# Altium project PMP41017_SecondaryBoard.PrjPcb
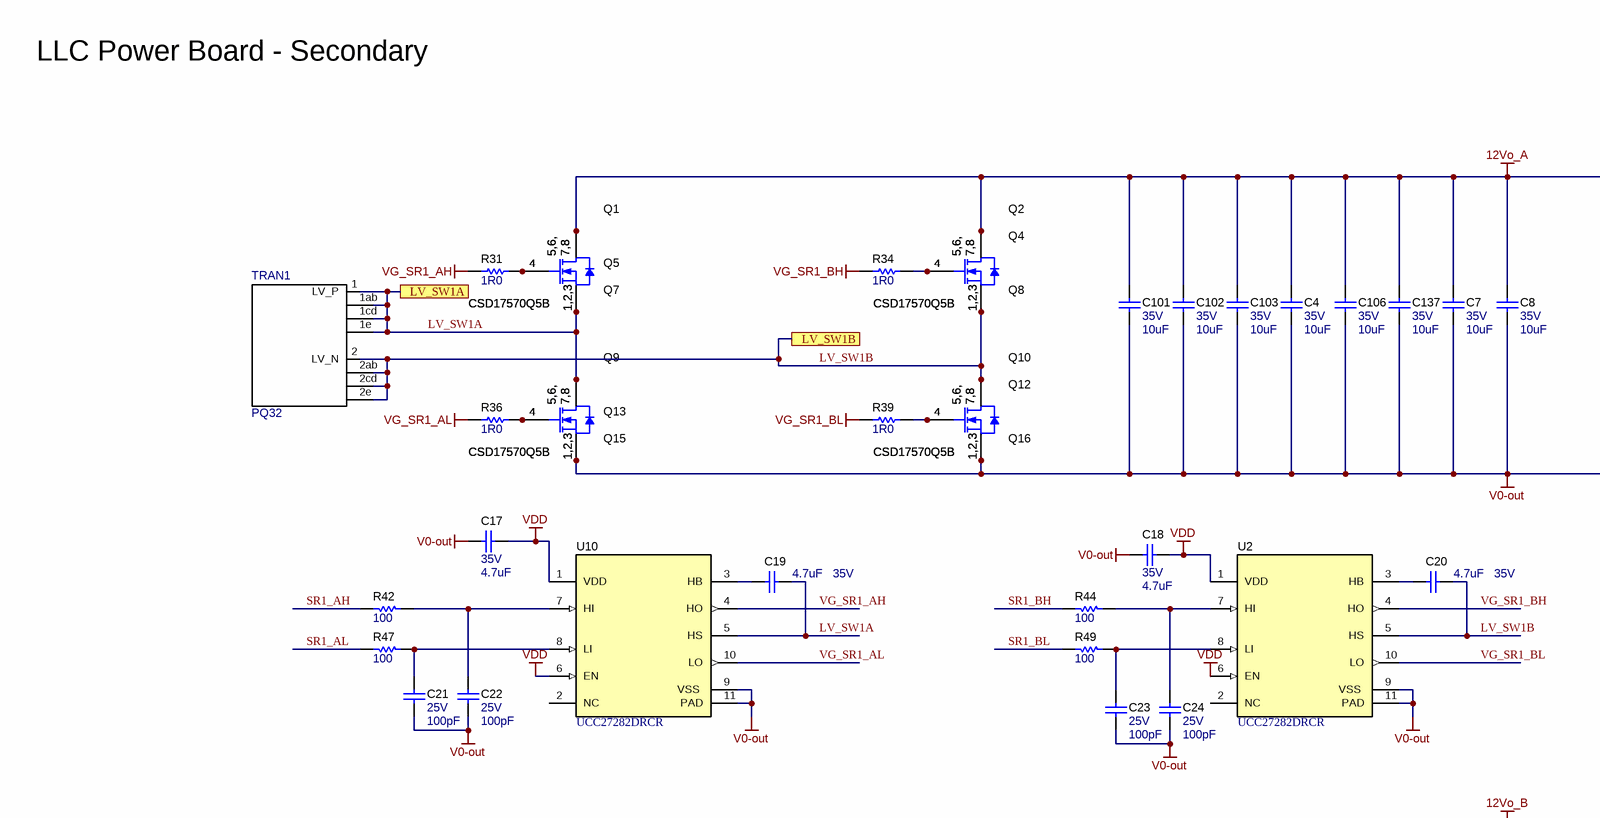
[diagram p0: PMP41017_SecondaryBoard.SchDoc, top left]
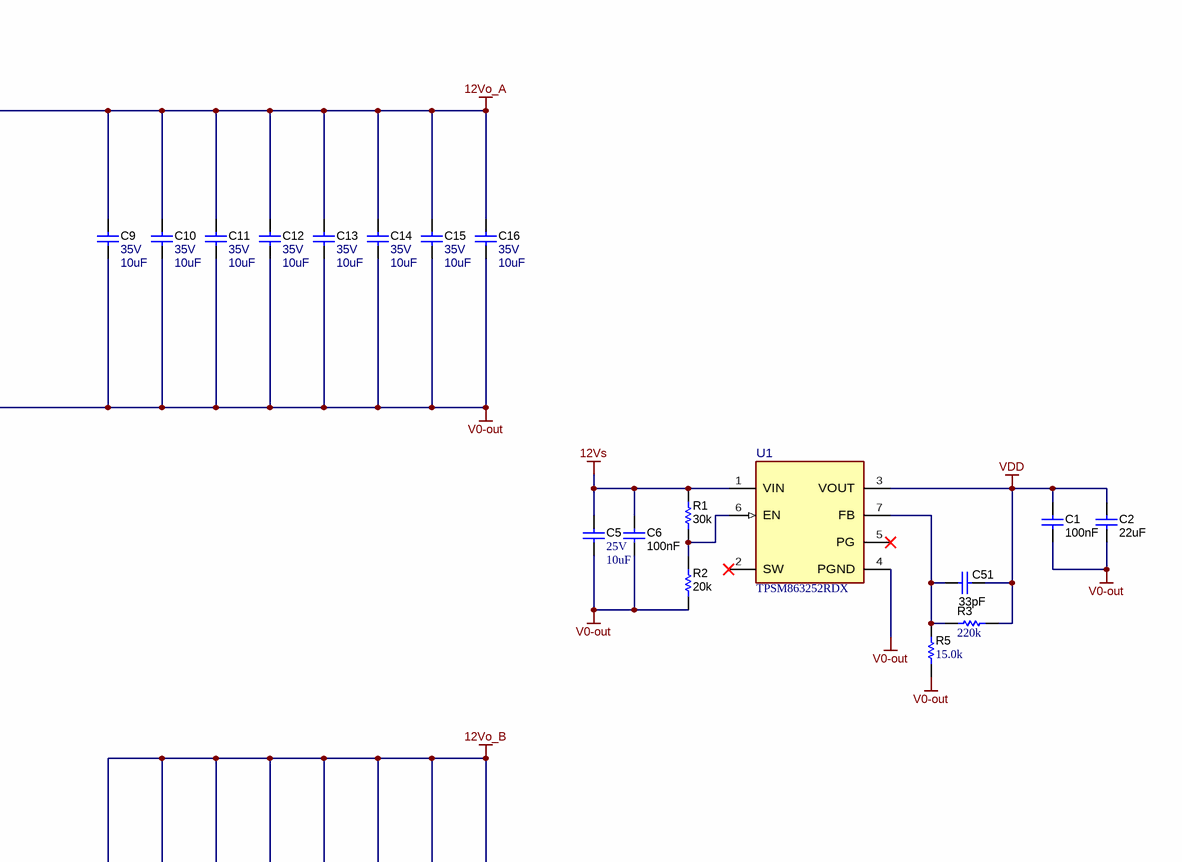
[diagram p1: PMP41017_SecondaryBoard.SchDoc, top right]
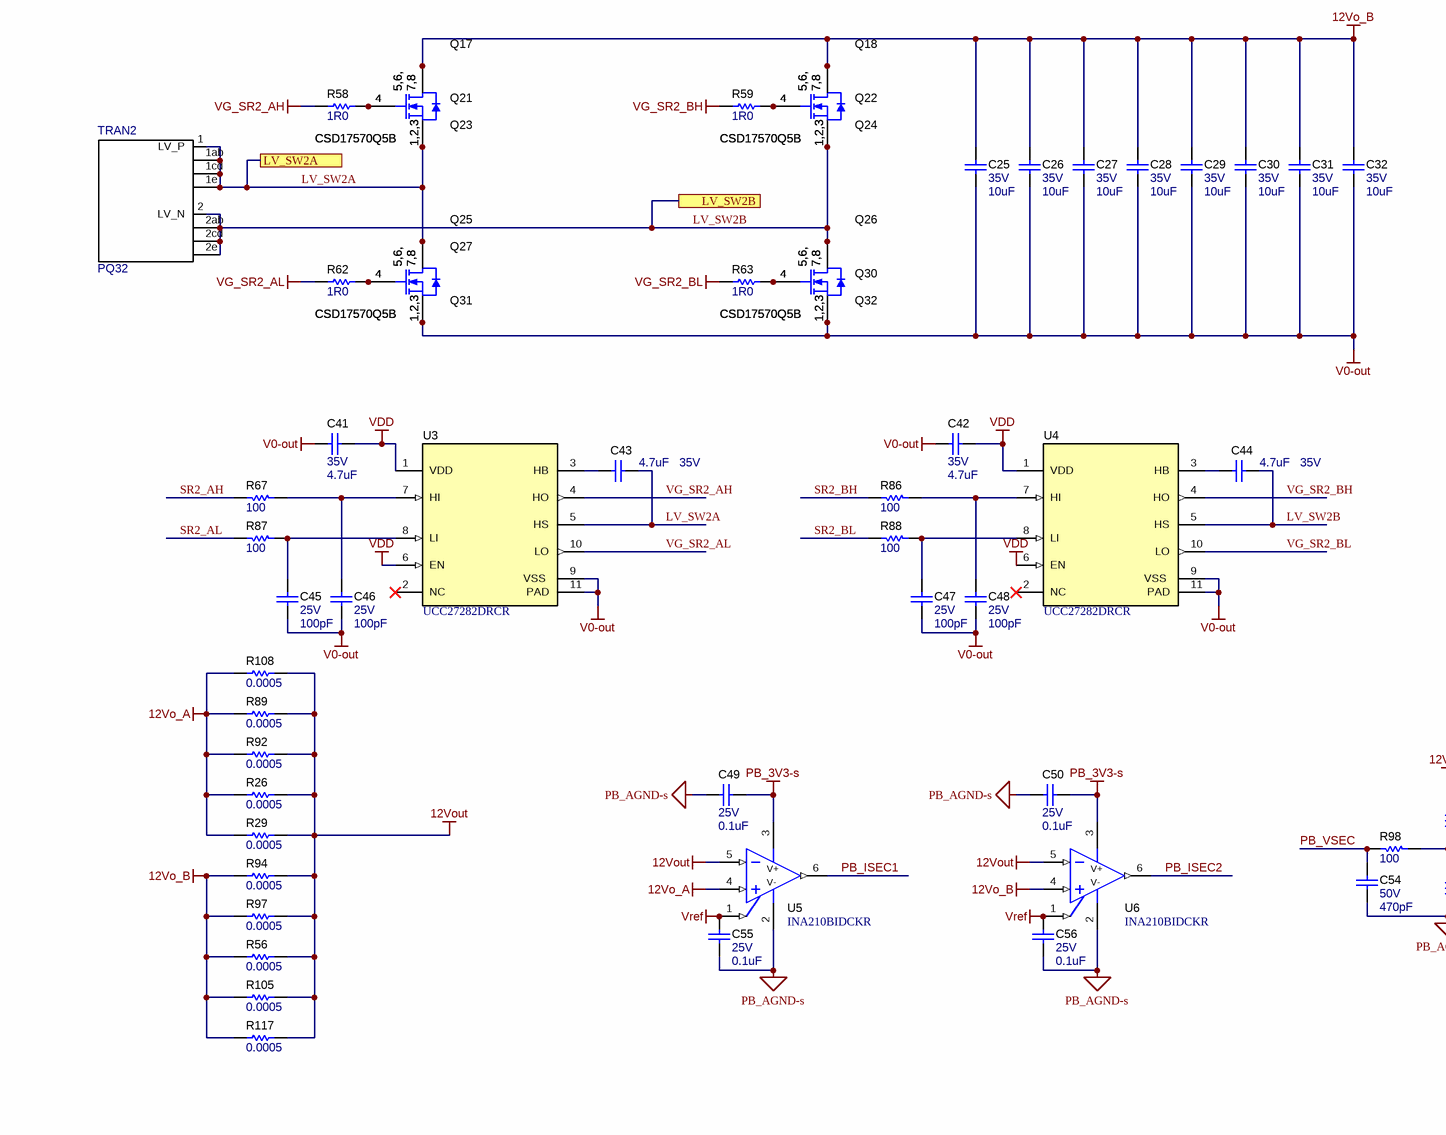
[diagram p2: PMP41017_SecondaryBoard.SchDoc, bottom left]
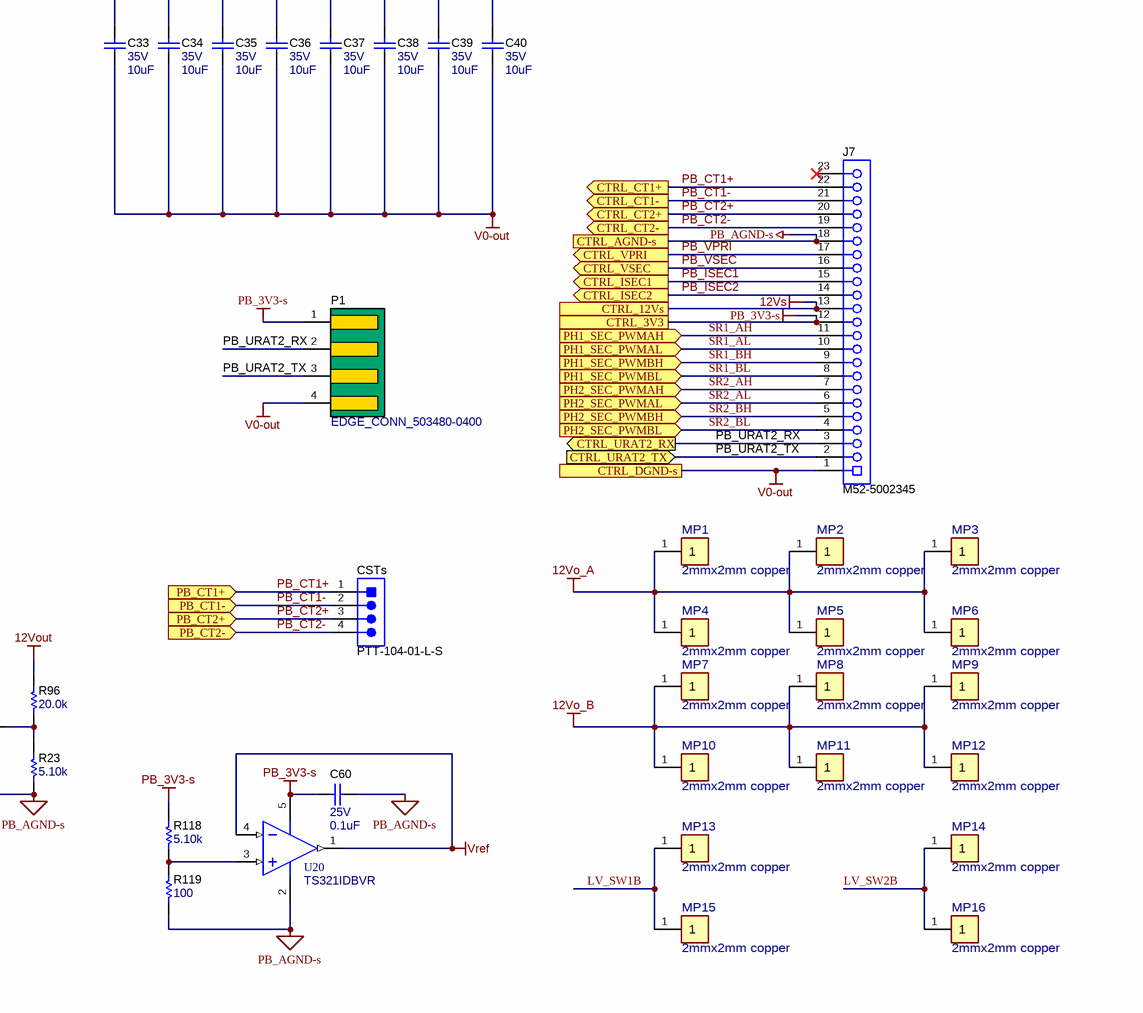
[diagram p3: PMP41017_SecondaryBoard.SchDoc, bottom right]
CopyrightYear: 2022; PCB_Layout: Desheng Guo; PCB_Rev: E1; PRJ_Customer: Public Release; PRJ_Engineer: Desheng Guo; PRJ_Number: PMP41017; PRJ_Title: CRPS 12V 3000W LLC; SCH_Rev: E1; TechSupport: http://www.ti.com/support; TID: N/A
1 sheet, 147 parts. Net scope: flat (ports and power ports of the same name join across sheets).
Board files: PMP41017_SecondaryBoard_Cyntec20230129.PcbDoc, PMP41017_SecondaryBoard.PcbDoc

## Sheet PMP41017_SecondaryBoard.SchDoc
size A2; Date: Not shown in title block; ApprovedBy: Not shown in title block; CheckedBy: Not shown in title block; Author: Not shown in title block; CompanyName: Not shown in title block; Engineer: Not shown in title block; Organization: Not shown in title block; Address1: Not shown in title block; Address2: Not shown in title block; Address3: Not shown in title block; Address4: Not shown in title block; DocumentNumber: 1; Revision: Use project parameter SCH_Rev; SheetNumber: 1; SheetTotal: 1; PageSetup: Record=PageOptions¦CenterHorizontal=True¦CenterVertical=True¦PrintScale=0.69¦XCorrection=1.00¦YCorrection=1.00¦PrintKind=0¦BorderSize=5000000¦LeftOffset=0¦BottomOffset=0¦Orientation=2¦PaperLength=1000¦PaperWidth=1000¦Scale=100¦PaperSource=15¦PrintQuality=600¦MediaType=1¦DitherType=10¦PaperKind=Letter¦PrintScaleMode=1

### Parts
C1  Cap_F: 100nF  [0603]  (hidden comment: C0603C104K5RACTU)
C2  ValueDisplayed: 22uF  [0805_HV]  (hidden comment: GRM21BC81C226ME44L)
C4  VDC_V: 35V  ValueDisplayed: 10uF  [1206_190]  (hidden comment: GMK316AB7106KL-TR)
C5  VDC_V: 25V  ValueDisplayed: 10uF  [0603]  (hidden comment: C1608X5R1E106M080AC)
C6  Cap_F: 100nF  [0603]  (hidden comment: C0603C104K5RACTU)
C7  VDC_V: 35V  ValueDisplayed: 10uF  [1206_190]  (hidden comment: GMK316AB7106KL-TR)
C8  VDC_V: 35V  ValueDisplayed: 10uF  [1206_190]  (hidden comment: GMK316AB7106KL-TR)
C9  VDC_V: 35V  ValueDisplayed: 10uF  [1206_190]  (hidden comment: GMK316AB7106KL-TR)
C10  VDC_V: 35V  ValueDisplayed: 10uF  [1206_190]  (hidden comment: GMK316AB7106KL-TR)
C11  VDC_V: 35V  ValueDisplayed: 10uF  [1206_190]  (hidden comment: GMK316AB7106KL-TR)
C12  VDC_V: 35V  ValueDisplayed: 10uF  [1206_190]  (hidden comment: GMK316AB7106KL-TR)
C13  VDC_V: 35V  ValueDisplayed: 10uF  [1206_190]  (hidden comment: GMK316AB7106KL-TR)
C14  VDC_V: 35V  ValueDisplayed: 10uF  [1206_190]  (hidden comment: GMK316AB7106KL-TR)
C15  VDC_V: 35V  ValueDisplayed: 10uF  [1206_190]  (hidden comment: GMK316AB7106KL-TR)
C16  VDC_V: 35V  ValueDisplayed: 10uF  [1206_190]  (hidden comment: GMK316AB7106KL-TR)
C17  VDC_V: 35V  ValueDisplayed: 4.7uF  [0805_HV]  (hidden comment: C2012X7R1V475K125AC)
C18  VDC_V: 35V  ValueDisplayed: 4.7uF  [0805_HV]  (hidden comment: C2012X7R1V475K125AC)
C19  VDC_V: 35V  ValueDisplayed: 4.7uF  [0805_HV]  (hidden comment: C2012X7R1V475K125AC)
C20  VDC_V: 35V  ValueDisplayed: 4.7uF  [0805_HV]  (hidden comment: C2012X7R1V475K125AC)
C21  VDC_V: 25V  ValueDisplayed: 100pF  [0603]  (hidden comment: CGA3E2C0G1H101J080AA)
C22  VDC_V: 25V  ValueDisplayed: 100pF  [0603]  (hidden comment: CGA3E2C0G1H101J080AA)
C23  VDC_V: 25V  ValueDisplayed: 100pF  [0603]  (hidden comment: CGA3E2C0G1H101J080AA)
C24  VDC_V: 25V  ValueDisplayed: 100pF  [0603]  (hidden comment: CGA3E2C0G1H101J080AA)
C25  VDC_V: 35V  ValueDisplayed: 10uF  [1206_190]  (hidden comment: GMK316AB7106KL-TR)
C26  VDC_V: 35V  ValueDisplayed: 10uF  [1206_190]  (hidden comment: GMK316AB7106KL-TR)
C27  VDC_V: 35V  ValueDisplayed: 10uF  [1206_190]  (hidden comment: GMK316AB7106KL-TR)
C28  VDC_V: 35V  ValueDisplayed: 10uF  [1206_190]  (hidden comment: GMK316AB7106KL-TR)
C29  VDC_V: 35V  ValueDisplayed: 10uF  [1206_190]  (hidden comment: GMK316AB7106KL-TR)
C30  VDC_V: 35V  ValueDisplayed: 10uF  [1206_190]  (hidden comment: GMK316AB7106KL-TR)
C31  VDC_V: 35V  ValueDisplayed: 10uF  [1206_190]  (hidden comment: GMK316AB7106KL-TR)
C32  VDC_V: 35V  ValueDisplayed: 10uF  [1206_190]  (hidden comment: GMK316AB7106KL-TR)
C33  VDC_V: 35V  ValueDisplayed: 10uF  [1206_190]  (hidden comment: GMK316AB7106KL-TR)
C34  VDC_V: 35V  ValueDisplayed: 10uF  [1206_190]  (hidden comment: GMK316AB7106KL-TR)
C35  VDC_V: 35V  ValueDisplayed: 10uF  [1206_190]  (hidden comment: GMK316AB7106KL-TR)
C36  VDC_V: 35V  ValueDisplayed: 10uF  [1206_190]  (hidden comment: GMK316AB7106KL-TR)
C37  VDC_V: 35V  ValueDisplayed: 10uF  [1206_190]  (hidden comment: GMK316AB7106KL-TR)
C38  VDC_V: 35V  ValueDisplayed: 10uF  [1206_190]  (hidden comment: GMK316AB7106KL-TR)
C39  VDC_V: 35V  ValueDisplayed: 10uF  [1206_190]  (hidden comment: GMK316AB7106KL-TR)
C40  VDC_V: 35V  ValueDisplayed: 10uF  [1206_190]  (hidden comment: GMK316AB7106KL-TR)
C41  VDC_V: 35V  ValueDisplayed: 4.7uF  [0805_HV]  (hidden comment: C2012X7R1V475K125AC)
C42  VDC_V: 35V  ValueDisplayed: 4.7uF  [0805_HV]  (hidden comment: C2012X7R1V475K125AC)
C43  VDC_V: 35V  ValueDisplayed: 4.7uF  [0805_HV]  (hidden comment: C2012X7R1V475K125AC)
C44  VDC_V: 35V  ValueDisplayed: 4.7uF  [0805_HV]  (hidden comment: C2012X7R1V475K125AC)
C45  VDC_V: 25V  ValueDisplayed: 100pF  [0603]  (hidden comment: CGA3E2C0G1H101J080AA)
C46  VDC_V: 25V  ValueDisplayed: 100pF  [0603]  (hidden comment: CGA3E2C0G1H101J080AA)
C47  VDC_V: 25V  ValueDisplayed: 100pF  [0603]  (hidden comment: CGA3E2C0G1H101J080AA)
C48  VDC_V: 25V  ValueDisplayed: 100pF  [0603]  (hidden comment: CGA3E2C0G1H101J080AA)
C49  VDC_V: 25V  ValueDisplayed: 0.1uF  [0603]  (hidden comment: C1608X7R1E104K080AA)
C50  VDC_V: 25V  ValueDisplayed: 0.1uF  [0603]  (hidden comment: C1608X7R1E104K080AA)
C51  ValueDisplayed: 33pF  [0603]  (hidden comment: GRM1885C2A330JA01D)
C54  VDC_V: 50V  ValueDisplayed: 470pF  [0603]  (hidden comment: C0603C471K5RACTU)
C55  VDC_V: 25V  ValueDisplayed: 0.1uF  [0603]  (hidden comment: C1608X7R1E104K080AA)
C56  VDC_V: 25V  ValueDisplayed: 0.1uF  [0603]  (hidden comment: C1608X7R1E104K080AA)
C60  VDC_V: 25V  ValueDisplayed: 0.1uF  [0603]  (hidden comment: C1608X7R1E104K080AA)
C101  VDC_V: 35V  ValueDisplayed: 10uF  [1206_190]  (hidden comment: GMK316AB7106KL-TR)
C102  VDC_V: 35V  ValueDisplayed: 10uF  [1206_190]  (hidden comment: GMK316AB7106KL-TR)
C103  VDC_V: 35V  ValueDisplayed: 10uF  [1206_190]  (hidden comment: GMK316AB7106KL-TR)
C106  VDC_V: 35V  ValueDisplayed: 10uF  [1206_190]  (hidden comment: GMK316AB7106KL-TR)
C137  VDC_V: 35V  ValueDisplayed: 10uF  [1206_190]  (hidden comment: GMK316AB7106KL-TR)
CSTs  PTT-104-01-L-S  [Samtec_PTT-104-01-x-S]  (no BOM)
J7  M52-5002345  [M52-5012345]  (no BOM)
MP1  2mmx2mm copper  [Copper 2x2]
MP2  2mmx2mm copper  [Copper 2x2]
MP3  2mmx2mm copper  [Copper 2x2]
MP4  2mmx2mm copper  [Copper 2x2]
MP5  2mmx2mm copper  [Copper 2x2]
MP6  2mmx2mm copper  [Copper 2x2]
MP7  2mmx2mm copper  [Copper 2x2]
MP8  2mmx2mm copper  [Copper 2x2]
MP9  2mmx2mm copper  [Copper 2x2]
MP10  2mmx2mm copper  [Copper 2x2]
MP11  2mmx2mm copper  [Copper 2x2]
MP12  2mmx2mm copper  [Copper 2x2]
MP13  2mmx2mm copper  [Copper 2x2]
MP14  2mmx2mm copper  [Copper 2x2]
MP15  2mmx2mm copper  [Copper 2x2]
MP16  2mmx2mm copper  [Copper 2x2]
P1  EDGE_CONN_503480-0400  [JAE_EDGE_CONN_503480-0400]  (no BOM)
Q1  CSD17570Q5B  [DNK0008A]
Q2  CSD17570Q5B  [DNK0008A]
Q4  CSD17570Q5B  [DNK0008A]
Q5  CSD17570Q5B  [DNK0008A]
Q7  CSD17570Q5B  [DNK0008A]
Q8  CSD17570Q5B  [DNK0008A]
Q9  CSD17570Q5B  [DNK0008A]
Q10  CSD17570Q5B  [DNK0008A]
Q12  CSD17570Q5B  [DNK0008A]
Q13  CSD17570Q5B  [DNK0008A]
Q15  CSD17570Q5B  [DNK0008A]
Q16  CSD17570Q5B  [DNK0008A]
Q17  CSD17570Q5B  [DNK0008A]
Q18  CSD17570Q5B  [DNK0008A]
Q21  CSD17570Q5B  [DNK0008A]
Q22  CSD17570Q5B  [DNK0008A]
Q23  CSD17570Q5B  [DNK0008A]
Q24  CSD17570Q5B  [DNK0008A]
Q25  CSD17570Q5B  [DNK0008A]
Q26  CSD17570Q5B  [DNK0008A]
Q27  CSD17570Q5B  [DNK0008A]
Q30  CSD17570Q5B  [DNK0008A]
Q31  CSD17570Q5B  [DNK0008A]
Q32  CSD17570Q5B  [DNK0008A]
R1  ValueDisplayed: 30k  [0603]  (hidden comment: CRCW060330K0JNEA)
R2  ValueDisplayed: 20k  [0603]  (hidden comment: CRCW060320K0JNEA)
R3  ValueDisplayed: 220k  [0603]  (hidden comment: RC0603FR-07220KL)
R5  ValueDisplayed: 15.0k  [0603]  (hidden comment: 15K 0603)
R23  ValueDisplayed: 5.10k  [0603]  (hidden comment: RC0603FR-075K1L)
R26  ValueDisplayed: 0.0005  [2512]  (hidden comment: CSNL2512FTL500)
R29  ValueDisplayed: 0.0005  [2512]  (hidden comment: CSNL2512FTL500)
R31  ValueDisplayed: 1R0  [0603]  (hidden comment: ERJ-3RQF1R0V)
R34  ValueDisplayed: 1R0  [0603]  (hidden comment: ERJ-3RQF1R0V)
R36  ValueDisplayed: 1R0  [0603]  (hidden comment: ERJ-3RQF1R0V)
R39  ValueDisplayed: 1R0  [0603]  (hidden comment: ERJ-3RQF1R0V)
R42  ValueDisplayed: 100  [0603]  (hidden comment: RC0603FR-07100RL)
R44  ValueDisplayed: 100  [0603]  (hidden comment: RC0603FR-07100RL)
R47  ValueDisplayed: 100  [0603]  (hidden comment: RC0603FR-07100RL)
R49  ValueDisplayed: 100  [0603]  (hidden comment: RC0603FR-07100RL)
R56  ValueDisplayed: 0.0005  [2512]  (hidden comment: CSNL2512FTL500)
R58  ValueDisplayed: 1R0  [0603]  (hidden comment: ERJ-3RQF1R0V)
R59  ValueDisplayed: 1R0  [0603]  (hidden comment: ERJ-3RQF1R0V)
R62  ValueDisplayed: 1R0  [0603]  (hidden comment: ERJ-3RQF1R0V)
R63  ValueDisplayed: 1R0  [0603]  (hidden comment: ERJ-3RQF1R0V)
R67  ValueDisplayed: 100  [0603]  (hidden comment: RC0603FR-07100RL)
R86  ValueDisplayed: 100  [0603]  (hidden comment: RC0603FR-07100RL)
R87  ValueDisplayed: 100  [0603]  (hidden comment: RC0603FR-07100RL)
R88  ValueDisplayed: 100  [0603]  (hidden comment: RC0603FR-07100RL)
R89  ValueDisplayed: 0.0005  [2512]  (hidden comment: CSNL2512FTL500)
R92  ValueDisplayed: 0.0005  [2512]  (hidden comment: CSNL2512FTL500)
R94  ValueDisplayed: 0.0005  [2512]  (hidden comment: CSNL2512FTL500)
R96  ValueDisplayed: 20.0k  [0603]  (hidden comment: RC0603FR-0720KL)
R97  ValueDisplayed: 0.0005  [2512]  (hidden comment: CSNL2512FTL500)
R98  ValueDisplayed: 100  [0603]  (hidden comment: RC0603FR-07100RL)
R105  ValueDisplayed: 0.0005  [2512]  (hidden comment: CSNL2512FTL500)
R108  ValueDisplayed: 0.0005  [2512]  (hidden comment: CSNL2512FTL500)
R117  ValueDisplayed: 0.0005  [2512]  (hidden comment: CSNL2512FTL500)
R118  ValueDisplayed: 5.10k  [0603]  (hidden comment: RC0603FR-075K1L)
R119  ValueDisplayed: 100  [0603]  (hidden comment: RC0603FR-07100RL)
TRAN1  PQ32  [86H-22072]
TRAN2  PQ32  [86H-22072]
U1  TPSM863252RDX  [RDX0007A-MFG]
U2  UCC27282DRCR  [DRC0010J]
U3  UCC27282DRCR  [DRC0010J]
U4  UCC27282DRCR  [DRC0010J]
U5  INA210BIDCKR  [DCK0006A_N]
U6  INA210BIDCKR  [DCK0006A_N]
U10  UCC27282DRCR  [DRC0010J]
U20  TS321IDBVR  [DBV0005A_L]

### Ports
CTRL_3V3, CTRL_12Vs, CTRL_AGND-s, CTRL_CT1+ (out), CTRL_CT1- (out), CTRL_CT2+ (out), CTRL_CT2- (out), CTRL_DGND-s, CTRL_ISEC1 (out), CTRL_ISEC2 (out), CTRL_URAT2_RX (out), CTRL_URAT2_TX (in), CTRL_VPRI (out), CTRL_VSEC (out), LV_SW1A, LV_SW1B, LV_SW2A, LV_SW2B, PB_CT1+ (in), PB_CT1- (in), PB_CT2+ (in), PB_CT2- (in), PH1_SEC_PWMAH (in), PH1_SEC_PWMAL (in), PH1_SEC_PWMBH (in), PH1_SEC_PWMBL (in), PH2_SEC_PWMAH (in), PH2_SEC_PWMAL (in), PH2_SEC_PWMBH (in), PH2_SEC_PWMBL (in)

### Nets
12Vo_A: C4.1 C7.1 C8.1 C9.1 C10.1 C11.1 C12.1 C13.1 C14.1 C15.1 C16.1 C101.1 C102.1 C103.1 C106.1 C137.1 MP1.1 MP2.1 MP3.1 MP4.1 MP5.1 MP6.1 Q1.5(D) Q1.6(D) Q1.7(D) Q1.8(D) Q1.9(D) Q2.5(D) Q2.6(D) Q2.7(D) Q2.8(D) Q2.9(D) Q4.5(D) Q4.6(D) Q4.7(D) Q4.8(D) Q4.9(D) Q5.5(D) Q5.6(D) Q5.7(D) Q5.8(D) Q5.9(D) Q7.5(D) Q7.6(D) Q7.7(D) Q7.8(D) Q7.9(D) Q8.5(D) Q8.6(D) Q8.7(D) Q8.8(D) Q8.9(D) R26.2 R29.2 R89.2 R92.2 R108.2 U5.4(IN+)
12Vo_B: C25.1 C26.1 C27.1 C28.1 C29.1 C30.1 C31.1 C32.1 C33.1 C34.1 C35.1 C36.1 C37.1 C38.1 C39.1 C40.1 MP7.1 MP8.1 MP9.1 MP10.1 MP11.1 MP12.1 Q17.5(D) Q17.6(D) Q17.7(D) Q17.8(D) Q17.9(D) Q18.5(D) Q18.6(D) Q18.7(D) Q18.8(D) Q18.9(D) Q21.5(D) Q21.6(D) Q21.7(D) Q21.8(D) Q21.9(D) Q22.5(D) Q22.6(D) Q22.7(D) Q22.8(D) Q22.9(D) Q23.5(D) Q23.6(D) Q23.7(D) Q23.8(D) Q23.9(D) Q24.5(D) Q24.6(D) Q24.7(D) Q24.8(D) Q24.9(D) R56.2 R94.2 R97.2 R105.2 R117.2 U6.4(IN+)
12Vout: R26.1 R29.1 R56.1 R89.1 R92.1 R94.1 R96.1 R97.1 R105.1 R108.1 R117.1 U5.5(IN-) U6.5(IN-)
12Vs: C5.1 C6.1 J7.13 R1.1 U1.1(VIN) ; port CTRL_12Vs
PB_3V3-s: C49.1 C50.1 C60.2 J7.12 P1.1 R118.2 U5.3(V+) U6.3(V+) U20.5(VCC+) ; port CTRL_3V3
PB_AGND-s: C49.2 C50.2 C54.2 C55.1 C56.1 C60.1 J7.18 R23.1 R119.1 U5.2(GND) U6.2(GND) U20.2(VCC-) ; port CTRL_AGND-s
V0-out: C1.2 C2.2 C4.2 C5.2 C6.2 C7.2 C8.2 C9.2 C10.2 C11.2 C12.2 C13.2 C14.2 C15.2 C16.2 C17.2 C18.2 C21.1 C22.1 C23.1 C24.1 C25.2 C26.2 C27.2 C28.2 C29.2 C30.2 C31.2 C32.2 C33.2 C34.2 C35.2 C36.2 C37.2 C38.2 C39.2 C40.2 C41.2 C42.2 C45.1 C46.1 C47.1 C48.1 C101.2 C102.2 C103.2 C106.2 C137.2 J7.1 P1.4 Q9.1(S) Q9.2(S) Q9.3(S) Q10.1(S) Q10.2(S) Q10.3(S) Q12.1(S) Q12.2(S) Q12.3(S) Q13.1(S) Q13.2(S) Q13.3(S) Q15.1(S) Q15.2(S) Q15.3(S) Q16.1(S) Q16.2(S) Q16.3(S) Q25.1(S) Q25.2(S) Q25.3(S) Q26.1(S) Q26.2(S) Q26.3(S) Q27.1(S) Q27.2(S) Q27.3(S) Q30.1(S) Q30.2(S) Q30.3(S) Q31.1(S) Q31.2(S) Q31.3(S) Q32.1(S) Q32.2(S) Q32.3(S) R2.2 R5.1 U1.4(PGND) U2.9(VSS) U2.11(PAD) U3.9(VSS) U3.11(PAD) U4.9(VSS) U4.11(PAD) U10.9(VSS) U10.11(PAD) ; port CTRL_DGND-s
VDD: C1.1 C2.1 C17.1 C18.1 C41.1 C42.1 C51.1 R3.2 U1.3(VOUT) U2.1(VDD) U2.6(EN) U3.1(VDD) U3.6(EN) U4.1(VDD) U4.6(EN) U10.1(VDD) U10.6(EN)
VG_SR1_AH: R31.1 U10.4(HO)
VG_SR1_AL: R36.1 U10.10(LO)
VG_SR1_BH: R34.1 U2.4(HO)
VG_SR1_BL: R39.1 U2.10(LO)
VG_SR2_AH: R58.1 U3.4(HO)
VG_SR2_AL: R62.1 U3.10(LO)
VG_SR2_BH: R59.1 U4.4(HO)
VG_SR2_BL: R63.1 U4.10(LO)
Vref: C55.2 C56.2 U5.1(REF) U6.1(REF) U20.1(OUT) U20.4(IN-)
LV_SW1A: C19.2 Q1.1(S) Q1.2(S) Q1.3(S) Q5.1(S) Q5.2(S) Q5.3(S) Q7.1(S) Q7.2(S) Q7.3(S) Q9.5(D) Q9.6(D) Q9.7(D) Q9.8(D) Q9.9(D) Q13.5(D) Q13.6(D) Q13.7(D) Q13.8(D) Q13.9(D) Q15.5(D) Q15.6(D) Q15.7(D) Q15.8(D) Q15.9(D) TRAN1.1(LV_P) TRAN1.1ab(LV_P) TRAN1.1cd(LV_P) TRAN1.1e(LV_P) U10.5(HS) ; port LV_SW1A
LV_SW1B: C20.2 MP13.1 MP15.1 Q2.1(S) Q2.2(S) Q2.3(S) Q4.1(S) Q4.2(S) Q4.3(S) Q8.1(S) Q8.2(S) Q8.3(S) Q10.5(D) Q10.6(D) Q10.7(D) Q10.8(D) Q10.9(D) Q12.5(D) Q12.6(D) Q12.7(D) Q12.8(D) Q12.9(D) Q16.5(D) Q16.6(D) Q16.7(D) Q16.8(D) Q16.9(D) TRAN1.2(LV_N) TRAN1.2ab(LV_P) TRAN1.2cd TRAN1.2e U2.5(HS) ; port LV_SW1B
LV_SW2A: C43.2 Q17.1(S) Q17.2(S) Q17.3(S) Q21.1(S) Q21.2(S) Q21.3(S) Q23.1(S) Q23.2(S) Q23.3(S) Q25.5(D) Q25.6(D) Q25.7(D) Q25.8(D) Q25.9(D) Q27.5(D) Q27.6(D) Q27.7(D) Q27.8(D) Q27.9(D) Q31.5(D) Q31.6(D) Q31.7(D) Q31.8(D) Q31.9(D) TRAN2.1(LV_P) TRAN2.1ab(LV_P) TRAN2.1cd(LV_P) TRAN2.1e(LV_P) U3.5(HS) ; port LV_SW2A
LV_SW2B: C44.2 MP14.1 MP16.1 Q18.1(S) Q18.2(S) Q18.3(S) Q22.1(S) Q22.2(S) Q22.3(S) Q24.1(S) Q24.2(S) Q24.3(S) Q26.5(D) Q26.6(D) Q26.7(D) Q26.8(D) Q26.9(D) Q30.5(D) Q30.6(D) Q30.7(D) Q30.8(D) Q30.9(D) Q32.5(D) Q32.6(D) Q32.7(D) Q32.8(D) Q32.9(D) TRAN2.2(LV_N) TRAN2.2ab(LV_P) TRAN2.2cd TRAN2.2e U4.5(HS) ; port LV_SW2B
PB_CT1+: CSTs.1 J7.22 ; port CTRL_CT1+, port PB_CT1+
PB_CT1-: CSTs.2 J7.21 ; port CTRL_CT1-, port PB_CT1-
PB_CT2+: CSTs.3 J7.20 ; port CTRL_CT2+, port PB_CT2+
PB_CT2-: CSTs.4 J7.19 ; port CTRL_CT2-, port PB_CT2-
PB_ISEC1: J7.15 U5.6(OUT) ; port CTRL_ISEC1
PB_ISEC2: J7.14 U6.6(OUT) ; port CTRL_ISEC2
PB_URAT2_RX: J7.3 P1.2 ; port CTRL_URAT2_RX
PB_URAT2_TX: J7.2 P1.3 ; port CTRL_URAT2_TX
PB_VPRI: J7.17 ; port CTRL_VPRI
PB_VSEC: C54.1 J7.16 R98.2 ; port CTRL_VSEC
SR1_AH: J7.11 R42.1 ; port PH1_SEC_PWMAH
SR1_AL: J7.10 R47.1 ; port PH1_SEC_PWMAL
SR1_BH: J7.9 R44.1 ; port PH1_SEC_PWMBH
SR1_BL: J7.8 R49.1 ; port PH1_SEC_PWMBL
SR2_AH: J7.7 R67.1 ; port PH2_SEC_PWMAH
SR2_AL: J7.6 R87.1 ; port PH2_SEC_PWMAL
SR2_BH: J7.5 R86.1 ; port PH2_SEC_PWMBH
SR2_BL: J7.4 R88.1 ; port PH2_SEC_PWMBL
NetC19_1: C19.1 U10.3(HB)
NetC20_1: C20.1 U2.3(HB)
NetC21_2: C21.2 R47.2 U10.8(LI)
NetC22_2: C22.2 R42.2 U10.7(HI)
NetC23_2: C23.2 R49.2 U2.8(LI)
NetC24_2: C24.2 R44.2 U2.7(HI)
NetC43_1: C43.1 U3.3(HB)
NetC44_1: C44.1 U4.3(HB)
NetC45_2: C45.2 R87.2 U3.8(LI)
NetC46_2: C46.2 R67.2 U3.7(HI)
NetC47_2: C47.2 R88.2 U4.8(LI)
NetC48_2: C48.2 R86.2 U4.7(HI)
NetC51_2: C51.2 R3.1 R5.2 U1.7(FB)
NetQ1_4: Q1.4(G) Q5.4(G) Q7.4(G) R31.2
NetQ2_4: Q2.4(G) Q4.4(G) Q8.4(G) R34.2
NetQ9_4: Q9.4(G) Q13.4(G) Q15.4(G) R36.2
NetQ10_4: Q10.4(G) Q12.4(G) Q16.4(G) R39.2
NetQ17_4: Q17.4(G) Q21.4(G) Q23.4(G) R58.2
NetQ18_4: Q18.4(G) Q22.4(G) Q24.4(G) R59.2
NetQ25_4: Q25.4(G) Q27.4(G) Q31.4(G) R62.2
NetQ26_4: Q26.4(G) Q30.4(G) Q32.4(G) R63.2
NetR1_2: R1.2 R2.1 U1.6(EN)
NetR23_2: R23.2 R96.2 R98.1
NetR118_1: R118.1 R119.2 U20.3(IN+)

Not connected (* = marked no-connect by the designer): J7 23(20)*; U1 2(SW)* 5(PG)*; U2 2(NC); U3 2(NC)*; U4 2(NC)*; U10 2(NC)

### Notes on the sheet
- LLC Power Board - Secondary

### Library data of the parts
C1 C6 = CMP-0006861-3: CAP, CERM, 0.1 uF, 50 V, +/- 10%, X7R, 0603; Manufacturer: Kemet; TaMin_C: -55°C; Polarized: N; SizeAreaWB_mm2: 4.68; Value1: Unknown; U/M: EA; Value: 0.1uF; TaMax_C: 125°C; SizeZ_mm: 1; SizeX_mm: 1.6; SizeY_mm: 0.8; Value2: 50V; SizeArea_mm2: 1.28; AEC Category: Q200
C2 = CMP-0008269-1: CAP, CERM, 22 uF, 16 V, +/- 20%, X6S, 0805; Manufacturer: MuRata; TaMin_C: -55°C; Polarized: N; SizeAreaWB_mm2: 6.75; Value1: Unknown; U/M: EA; Value: 22uF; TaMax_C: 105°C; SizeZ_mm: 1.45; SizeX_mm: 2; SizeY_mm: 1.25; Cap_Case: 0805; Value2: 16V; SizeArea_mm2: 2.5; Cap_F: 22µF; AEC Category: Q200
C4 C7-C16 C25-C40 C101-C103 C106 C137 = CMP-0008822-2: CAP, CERM, 10 uF, 35 V, +/- 10%, X7R, 1206_190; Manufacturer: Taiyo Yuden; TaMin_C: -55°C; Polarized: N; SizeAreaWB_mm2: 10.92; Value1: Unknown; U/M: EA; Value: 10uF; TaMax_C: 125°C; SizeZ_mm: 1.9; SizeX_mm: 3.2; SizeY_mm: 1.6; Cap_Case: 1206; SizeArea_mm2: 5.12; Cap_F: 10µF; AEC Category: Q200
C5 = CMP-0007007-5: CAP, CERM, 10 uF, 25 V, +/- 20%, X5R, 0603; Manufacturer: TDK; TaMin_C: -55°C; ESR_ohm: 4.639m; Polarized: N; SizeAreaWB_mm2: 4.68; Value1: 0.004639 ohm; U/M: EA; Value: 10uF; TaMax_C: 85°C; SizeZ_mm: 1; SizeX_mm: 1.6; SizeY_mm: 0.8; SizeArea_mm2: 1.28; Cap_F: 10µF; IRMS_A: 2.41407A; AEC Category: Q200
C17-C20 C41-C44 = CMP-0007885-2: CAP, CERM, 4.7 uF, 35 V, +/- 10%, X7R, 0805; Manufacturer: TDK; TaMin_C: -55°C; ESR_ohm: 2.346m; Polarized: N; SizeAreaWB_mm2: 6.75; Value1: 0.002346 ohm; U/M: EA; Value: 4.7uF; TaMax_C: 125°C; SizeZ_mm: 1.45; SizeX_mm: 2; SizeY_mm: 1.25; Cap_Case: 0805; SizeArea_mm2: 2.5; Cap_F: 4.7µF; IRMS_A: 4.26021A; AEC Category: Q200
C21-C24 C45-C48 = CMP-0006751-4: CAP, CERM, 100 pF, 25 V, +/- 10%, X7R, 0603; Manufacturer: Samsung; PartNumber: CL10B101KB8NNNC; TaMin_C: -55°C; Polarized: N; SizeAreaWB_mm2: 4.68; Value1: Unknown; U/M: EA; Value: 100pF; TaMax_C: 125°C; SizeZ_mm: 1; SizeX_mm: 1.6; SizeY_mm: 0.8; SizeArea_mm2: 1.28; AEC Category: Q200
C49 C50 C55 C56 C60 = CMP-0007039-5: CAP, CERM, 0.1 uF, 25 V, +/- 10%, X7R, 0603; Manufacturer: TDK; TaMin_C: -55°C; Polarized: N; SizeAreaWB_mm2: 4.68; Value1: Unknown; U/M: EA; Value: 0.1uF; TaMax_C: 125°C; SizeZ_mm: 1; SizeX_mm: 1.6; SizeY_mm: 0.8; SizeArea_mm2: 1.28; Cap_F: 100nF; AEC Category: Q200
C51 = CMP-0007263-3: CAP, CERM, 33 pF, 100 V, +/- 5%, C0G/NP0, 0603; Manufacturer: MuRata; TaMin_C: -55°C; Polarized: N; SizeAreaWB_mm2: 4.68; Value1: Unknown; U/M: EA; Value: 33pF; TaMax_C: 125°C; SizeZ_mm: 1; SizeX_mm: 1.6; SizeY_mm: 0.8; Value2: 100V; SizeArea_mm2: 1.28; AEC Category: Q200
C54 = CMP-0007455-4: CAP, CERM, 470 pF, 50 V, +/- 10%, X7R, 0603; Manufacturer: KEMET; TaMin_C: -55°C; Polarized: N; SizeAreaWB_mm2: 4.68; Value1: Unknown; U/M: EA; Value: 470pF; TaMax_C: 125°C; SizeZ_mm: 1; SizeX_mm: 1.6; SizeY_mm: 0.8; SizeArea_mm2: 1.28; AEC Category: Q200
CSTs = CMP-0055572-1: Header, 2mm, 4x1, Gold, TH; Manufacturer: Samtec; CNHeader: TRUE; Current_A: 2.9A; Shrouded: N; Gender: Male; Row_Count: 1; Pitch_mm: 2; CT: FALSE; Cert_UL: Y
J7 = Receptacle_23x1: Receptacle, 23x1, 1.27mm, TH; Manufacturer: Harwin Inc.; CT: False; CompType: Socket
MP1-MP16 = SYM-9774025243R: Spacer, SMT, Swage Round, Steel, 2x2mm; PartNumber: 2mmx2mmx2mm
P1 = CMP-0055349-1: Edge Connector, 0.5 mm, 4x1, SMT; Manufacturer: Molex; CT: TRUE; CompType: Card Edge Footprint; CNHeader: FALSE
Q1 Q2 Q4 Q5 Q7-Q10 Q12 Q13 Q15-Q18 Q21-Q27 Q30-Q32 = CMP-0000586-2: MOSFET, N-CH, 30 V, 100 A, DNK0008A (VSON-CLIP-8); Alternate Manufacturer: None; Manufacturer: Texas Instruments; SizeZ_mm: 1; ChType: N; Value2: 49 nC; Value1: 0.0014; VdsMax_V: 30V; SizeX_mm: 6; SizeY_mm: 5; Vgs_V: 20V; Value: 30V; Rdson45_ohm: 1.45m; SizeArea_mm2: 30; AEC Category: Q101; IdsMax_A: 100A; SizeAreaWB_mm2: 56; U/M: EA; QgTyp_nC: 49
R1 = CMP-0025782-1: RES, 30 k, 5%, 0.1 W, 0603; Manufacturer: Vishay-Dale; Power_W: 100mW; TempCo: 200 ppm/C; Value_Code: 30k0; U/M: EA; Value: 30k; EIA_Code: E24; SizeX_mm: 1.6; SizeY_mm: 0.8; SizeZ_mm: 1; Value2: 0.1W; SizeArea_mm2: 1.28; VDC_V: 75V; AEC Category: Q200
R2 = CMP-0025753-3: RES, 20 k, 5%, 0.1 W, 0603; Manufacturer: Vishay-Dale; Power_W: 100mW; TempCo: 200 ppm/C; Value_Code: 20k0; U/M: EA; Value: 20k; EIA_Code: E24; SizeX_mm: 1.6; SizeY_mm: 0.8; SizeZ_mm: 1; Value2: 0.1W; SizeArea_mm2: 1.28; VDC_V: 75V; AEC Category: Q200
R3 = CMP-0022917-4: RES, 220 k, 1%, 0.1 W, 0603; Manufacturer: Yageo; Power_W: 100mW; TempCo: 100 ppm/C; Value: 220k; SizeX_mm: 1.6; SizeY_mm: 0.8; SizeZ_mm: 1; Value2: 0.1W; SizeArea_mm2: 1.28; AEC Qualified: N; VDC_V: 75V; AEC Category: Q200; SizeAreaWB_mm2: 4.68
R5 = CMP-0023020-5: RES, 15.0 k, 1%, 0.1 W, 0603; Manufacturer: Yageo; Power_W: 100mW; TempCo: 100 ppm/C; Value_Code: 15k0; Value: 15.0k; SizeX_mm: 1.6; SizeY_mm: 0.8; SizeZ_mm: 1; Value2: 0.1W; SizeArea_mm2: 1.28; AEC Qualified: N; VDC_V: 75V; AEC Category: Q200; SizeAreaWB_mm2: 4.68
R23 R118 = CMP-0023198-5: RES, 5.10 k, 1%, 0.1 W, 0603; Manufacturer: Yageo; Power_W: 100mW; TempCo: 100 ppm/C; Value_Code: 5k10; Value: 5.10k; Res_ohm: 5.1k; SizeX_mm: 1.6; SizeY_mm: 0.8; SizeZ_mm: 1; Value2: 0.1W; SizeArea_mm2: 1.28; AEC Qualified: N; VDC_V: 75V; AEC Category: Q200; SizeAreaWB_mm2: 4.68
R26 R29 R56 R89 R92 R94 R97 R105 R108 R117 = CMP-0015817-2: RES, 0.0005, 1%, 2 W, 2512; Manufacturer: Stackpole Electronics Inc; Power_W: 3W; TempCo: ppm/C; Value_Code: 1L000; U/M: EA; Value: 0.0005; EIA_Code: E96; Res_ohm: 1m; SizeX_mm: 6.3; SizeY_mm: 3.2; SizeZ_mm: 0.71; Value2: 2W; SizeArea_mm2: 20.16; AEC Category: Q200
R31 R34 R36 R39 R58 R59 = CMP-0022711-2: RES, 1ohm 1%, 0.1 W, 0603; Manufacturer: Panasonic; PartNumber: ERJ-3RQF2R2V; Power_W: 100mW; TempCo: 200 ppm/C; Value_Code: 1R; U/M: EA; Value: 1.0; Res_ohm: 1; SizeX_mm: 1.6; SizeY_mm: 0.8; Value2: 0.1W; SizeArea_mm2: 1.28; AEC Category: Q200
R42 R44 R47 R49 R67 R86-R88 R98 R119 = CMP-0022736-4: RES, 100, 1%, 0.1 W, 0603; Manufacturer: Yageo; Power_W: 100mW; TempCo: 100 ppm/C; Value_Code: 100R; Value: 100; EIA_Code: E96; SizeX_mm: 1.6; SizeY_mm: 0.8; SizeZ_mm: 1; Value2: 0.1W; SizeArea_mm2: 1.28; AEC Qualified: N; VDC_V: 75V; AEC Category: Q200; SizeAreaWB_mm2: 4.68
R62 R63 = CMP-0022711-2: RES, 1ohm 1%, 0.1 W, 0603; Manufacturer: Panasonic; PartNumber: ERJ-3RQF2R2V; Power_W: 100mW; TempCo: 200 ppm/C; Value_Code: 2R20; U/M: EA; Value: 1.0; SizeX_mm: 1.6; SizeY_mm: 0.8; SizeZ_mm: 1; Value2: 0.1W; SizeArea_mm2: 1.28; AEC Category: Q200
R96 = CMP-0022906-5: RES, 20.0 k, 1%, 0.1 W, 0603; Manufacturer: Yageo; Power_W: 100mW; TempCo: 100 ppm/C; Value_Code: 20k0; Value: 20.0k; EIA_Code: E96; Res_ohm: 20k; SizeX_mm: 1.6; SizeY_mm: 0.8; SizeZ_mm: 1; Value2: 0.1W; SizeArea_mm2: 1.28; AEC Qualified: N; VDC_V: 75V; AEC Category: Q200; SizeAreaWB_mm2: 4.68
TRAN1 TRAN2 = Transformer_sec: PQ32 TRANSFORMER; Manufacturer: YAXIN ELECTRONIC TECH; SymbolCreator: Use LDAP id; SymbolVersion: use current date i.e. 2008-05-20
U1 = CMP-0097277-1: 3V to 16 V Input, 3-A Synchronous Step-Down Voltage Regulator Module, QFN-FCMOD7; Manufacturer: Texas Instruments; Nominal Supply Current: 120-400uA; SizeZ_mm: 2.1mm; AEC Qualified: No; Output Type: AdjustableProgrammable; Switching Topology: Buck; AEC Grade: NA; Standoff Height: 0mm; Max Supply Voltage: 16V; Number Of Outputs: 1; Switching Frequency: 1400/2000kHz; TJmax_C: +125°C; Max Duty Cycle: 98%; Output Voltage: 0.6-7V
U2-U4 U10 = CMP-0013393-6: 120-V, 3-A Peak, 5-V UVLO, 3x3, High-Frequency, High-Side/Low-Side Driver, DRC0010J (VSON-10); Manufacturer: Texas Instruments; SizeAreaWB_mm2: 16; SizeZ_mm: 1; SizeX_mm: 3; SizeArea_mm2: 9; CompType: IC; Rating: Catalog; AEC Qualified: N; AEC Category: Q200
U5 U6 = CMP-0075733-4: 26-V, Bi-Directional, Zero-Drift, High Accuracy, Low-/High-Side, Voltage Out Current Shunt Monitor, DCK0006A (SOT-SC70-6); Alternate PartNumber: INA210BIDCKT; Manufacturer: Texas Instruments; SizeX_mm: 2.1; SizeY_mm: 2.0; SizeAreaWB_mm2: 9.3; AEC Category: Q200; AEC Qualified: N; Rating: Catalog; CompType: IC; SizeZ_mm: 1.1; SizeArea_mm2: 4.2
U20 = CMP-0043733-1: Low-Power Single Operational Amplifier, 3 to 30 V, -40 to 125 degC, 5-pin SOT23 (DBV5), Green (RoHS & no Sb/Br); Manufacturer: Texas Instruments; Iq per channel(Max)(mA): 1; Sub Family: General Purpose Amplifier, High Supply Voltage Amplifier (>=30V); CMRR(Min)(dB): 65; Total Supply Voltage(Max)(+5V is 5, +/-5V is 10): 30; Slew Rate(Typ)(V/us): 0.4; Vio (25C)(Max)(mV): 4; GBW(Typ)(MHz): 0.8; IIB(Max)(pA): 200000; Vn at 1kHz(Typ)(nV/rtHz): 50; Total Supply Voltage(Min)(+5V is 5, +/-5V is 10): 3

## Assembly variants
001: not fitted FID1 FID2 FID3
